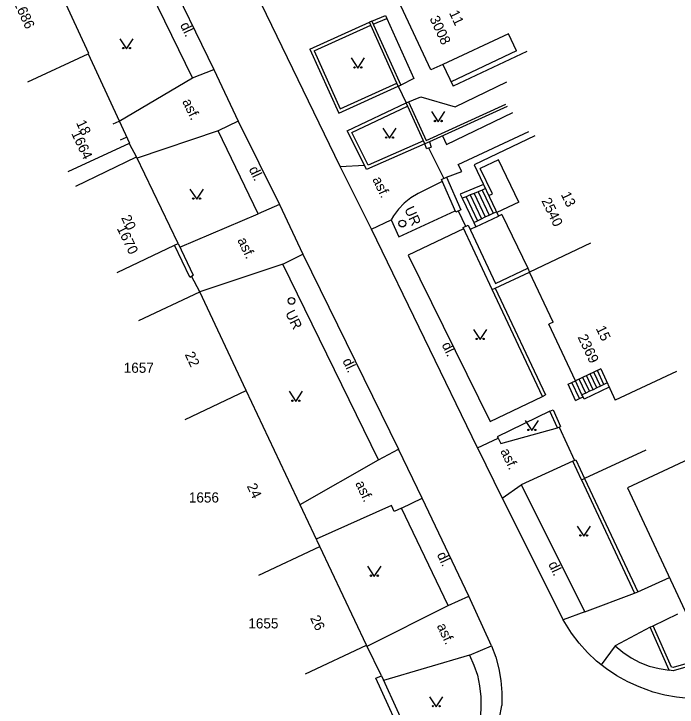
# Model space of a CAD drawing. Extents: x -584400 to -581602, y -1210894 to -1208793.
# Drawn here: x -583212.7 to -583163.5, y -1209753.8 to -1209702.4 of the extents above; entities that cross this region are included whole.
import ezdxf

# ---------------------------------------------------------------- set-up
doc = ezdxf.new("R2010")
doc.units = 0
for name, color, linetype in [('BUDOVY_MĚŘ', 7, 'Continuous'), ('POMOC_POPIS', 7, 'Continuous'), ('ROZHRANÍ_PLOCH', 7, 'Continuous'), ('ZN_DOPLŇKOVÉ', 7, 'Continuous'), ('ZN_KULTUR', 7, 'Continuous'), ('Č_POPIS_EVID', 7, 'Continuous')]:
    doc.layers.add(name, color=color, linetype=linetype)

msp = doc.modelspace()

# ---------------------------------------------------------------- linework, layer by layer
at = {"layer": 'BUDOVY_MĚŘ'}
for points in [[(-583207.21, -1209705.38), (-583207.17, -1209705.36), (-583212.56, -1209693.7)], [(-583180.91, -1209706.16), (-583181.8, -1209706.57), (-583185.32, -1209699.05)], [(-583211.7, -1209707.46), (-583207.21, -1209705.38)], [(-583207.21, -1209705.38), (-583204.16, -1209712)], [(-583174.69, -1209705.2), (-583180.16, -1209707.76)], [(-583180.91, -1209706.16), (-583180.16, -1209707.76)], [(-583174.09, -1209711.44), (-583178.6, -1209713.59), (-583176.78, -1209717.39)], [(-583208.71, -1209714.09), (-583204.16, -1209712)], [(-583208.13, -1209715.17), (-583203.63, -1209713.01)], [(-583205.06, -1209721.58), (-583200.82, -1209719.55), (-583200.55, -1209719.42), (-583203.63, -1209713.01)], [(-583176.55, -1209717.28), (-583176.78, -1209717.39)], [(-583176.55, -1209717.28), (-583174.62, -1209721.26), (-583174.49, -1209721.54)], [(-583169.96, -1209719.41), (-583174.49, -1209721.54)], [(-583172.74, -1209725.25), (-583174.49, -1209721.54)], [(-583203.47, -1209725.14), (-583198.94, -1209723.01)], [(-583195.49, -1209730.33), (-583198.94, -1209723.01)], [(-583172.74, -1209725.25), (-583173.06, -1209725.4)], [(-583169.21, -1209728.72), (-583171.08, -1209729.6), (-583173.06, -1209725.4)], [(-583169.21, -1209728.72), (-583168.13, -1209731.04)], [(-583163.6, -1209728.92), (-583168.13, -1209731.04)], [(-583200.02, -1209732.46), (-583195.49, -1209730.33)], [(-583190.04, -1209741.87), (-583195.49, -1209730.33)], [(-583162.69, -1209735.4), (-583167.22, -1209737.52), (-583162.6, -1209747.4)], [(-583194.56, -1209744.01), (-583190.04, -1209741.87)], [(-583191.1, -1209751.32), (-583186.58, -1209749.18), (-583190.04, -1209741.87)]]:
    msp.add_lwpolyline(points, dxfattribs=at)
at = {"layer": 'ROZHRANÍ_PLOCH'}
for points in [[(-583188.54, -1209713.73), (-583206.86, -1209675.87), (-583209.5, -1209670.38)], [(-583201.53, -1209699.05), (-583197.9, -1209706.54)], [(-583199.49, -1209707.15), (-583203.06, -1209699.78)], [(-583186.19, -1209702.95), (-583185.18, -1209702.53), (-583185.08, -1209702.76)], [(-583186.08, -1209703.18), (-583185.08, -1209702.76)], [(-583185.08, -1209702.76), (-583183.06, -1209707.21), (-583184.04, -1209707.69)], [(-583190.79, -1209705.03), (-583186.36, -1209703.03)], [(-583190.46, -1209705.15), (-583186.26, -1209703.25)], [(-583175.45, -1209705.16), (-583176.05, -1209703.88), (-583180.91, -1209706.16)], [(-583190.79, -1209705.03), (-583188.64, -1209709.77), (-583184.22, -1209707.77), (-583183.63, -1209709.01)], [(-583190.46, -1209705.15), (-583188.52, -1209709.44), (-583184.32, -1209707.54)], [(-583175.45, -1209705.16), (-583180.31, -1209707.44)], [(-583199.49, -1209707.15), (-583197.9, -1209706.54)], [(-583197.9, -1209706.54), (-583196.1, -1209710.36)], [(-583204.92, -1209710.36), (-583199.49, -1209707.15)], [(-583183.63, -1209709.01), (-583182.54, -1209708.57), (-583180.01, -1209709.29), (-583176.18, -1209707.45)], [(-583186.73, -1209713.63), (-583188.01, -1209711.07), (-583183.63, -1209709.01)], [(-583182.36, -1209711.81), (-583186.46, -1209713.62), (-583187.67, -1209711.19), (-583183.53, -1209709.24)], [(-583180.94, -1209711.44), (-583180.64, -1209712.08), (-583175.73, -1209709.71)], [(-583205.37, -1209710.57), (-583204.92, -1209710.36)], [(-583196.1, -1209710.36), (-583197.59, -1209711.08)], [(-583196.1, -1209710.36), (-583193.03, -1209716.54)], [(-583197.59, -1209711.08), (-583203.58, -1209713.1)], [(-583194.6, -1209717.23), (-583197.59, -1209711.08)], [(-583180.65, -1209714.52), (-583179.52, -1209714.08), (-583179.77, -1209713.57), (-583174.53, -1209711.14)], [(-583204.83, -1209711.75), (-583204.37, -1209711.54)], [(-583182.26, -1209712.04), (-583186.58, -1209713.94), (-583186.73, -1209713.63)], [(-583188.54, -1209713.73), (-583186.73, -1209713.63)], [(-583175.29, -1209716.37), (-583176.79, -1209713.22), (-583178.14, -1209713.86)], [(-583186.22, -1209718.37), (-583188.54, -1209713.73)], [(-583177.51, -1209715.87), (-583177.24, -1209715.74), (-583178.14, -1209713.86)], [(-583180.97, -1209714.83), (-583182.76, -1209715.72), (-583183.29, -1209716.04), (-583183.78, -1209716.43), (-583184.2, -1209716.88), (-583184.57, -1209717.38), (-583184.74, -1209717.68)], [(-583177.9, -1209715.05), (-583179.63, -1209715.77), (-583179.48, -1209716.08)], [(-583178.6, -1209715.71), (-583178.89, -1209715.83)], [(-583178.3, -1209715.59), (-583178.6, -1209715.71)], [(-583178.6, -1209715.71), (-583177.77, -1209717.46)], [(-583178.01, -1209715.47), (-583178.3, -1209715.59)], [(-583178.3, -1209715.59), (-583177.48, -1209717.32)], [(-583177.76, -1209715.36), (-583178.01, -1209715.47)], [(-583178.01, -1209715.47), (-583177.19, -1209717.19)], [(-583179.19, -1209715.96), (-583179.48, -1209716.08)], [(-583179.48, -1209716.08), (-583178.63, -1209717.88)], [(-583178.89, -1209715.83), (-583179.19, -1209715.96)], [(-583179.19, -1209715.96), (-583178.35, -1209717.74)], [(-583178.89, -1209715.83), (-583178.06, -1209717.6)], [(-583193.03, -1209716.54), (-583194.6, -1209717.23)], [(-583193.03, -1209716.54), (-583191.29, -1209720.21)], [(-583175.29, -1209716.37), (-583176.91, -1209717.14)], [(-583200.42, -1209719.69), (-583194.6, -1209717.23)], [(-583184.74, -1209717.68), (-583184.17, -1209718.93), (-583180, -1209717.01)], [(-583177.48, -1209717.32), (-583177.19, -1209717.19)], [(-583177.19, -1209717.19), (-583176.94, -1209717.07)], [(-583186.22, -1209718.37), (-583184.74, -1209717.68)], [(-583178.63, -1209717.88), (-583178.35, -1209717.74)], [(-583178.48, -1209718.2), (-583176.78, -1209717.39)], [(-583178.35, -1209717.74), (-583178.06, -1209717.6)], [(-583178.06, -1209717.6), (-583177.77, -1209717.46)], [(-583177.77, -1209717.46), (-583177.48, -1209717.32)], [(-583178.48, -1209718.2), (-583178.89, -1209718.38)], [(-583178.63, -1209717.88), (-583178.48, -1209718.2)], [(-583178.35, -1209734.57), (-583186.22, -1209718.37)], [(-583179.38, -1209718.34), (-583183.48, -1209720.29), (-583177.41, -1209732.62), (-583173.53, -1209730.76)], [(-583192.78, -1209720.96), (-583191.29, -1209720.21)], [(-583191.29, -1209720.21), (-583184.21, -1209734.66)], [(-583192.78, -1209720.96), (-583198.94, -1209723.01)], [(-583185.7, -1209735.45), (-583192.78, -1209720.96)], [(-583169.51, -1209730.13), (-583170, -1209729.09)], [(-583169.24, -1209730), (-583169.73, -1209728.96)], [(-583168.97, -1209729.87), (-583169.45, -1209728.84)], [(-583171.36, -1209729.73), (-583171.08, -1209729.6)], [(-583170.6, -1209730.64), (-583171.08, -1209729.6)], [(-583170.32, -1209730.51), (-583170.81, -1209729.47)], [(-583170.05, -1209730.38), (-583170.54, -1209729.35)], [(-583169.78, -1209730.26), (-583170.27, -1209729.22)], [(-583171.07, -1209731.05), (-583171.63, -1209729.86), (-583171.36, -1209729.73)], [(-583170.79, -1209730.92), (-583171.36, -1209729.73)], [(-583168.58, -1209730.08), (-583170.45, -1209730.96), (-583170.52, -1209730.8)], [(-583169.51, -1209730.13), (-583169.78, -1209730.26)], [(-583169.24, -1209730), (-583169.51, -1209730.13)], [(-583168.97, -1209729.87), (-583169.24, -1209730)], [(-583168.73, -1209729.76), (-583168.97, -1209729.87)], [(-583170.32, -1209730.51), (-583170.6, -1209730.64)], [(-583170.52, -1209730.8), (-583170.6, -1209730.64)], [(-583170.05, -1209730.38), (-583170.32, -1209730.51)], [(-583169.78, -1209730.26), (-583170.05, -1209730.38)], [(-583171.07, -1209731.05), (-583170.79, -1209730.92)], [(-583170.79, -1209730.92), (-583170.52, -1209730.8)], [(-583172.98, -1209731.84), (-583176.88, -1209733.75), (-583176.82, -1209733.86)], [(-583176.82, -1209733.86), (-583176.63, -1209734.25), (-583172.42, -1209733.08)], [(-583178.35, -1209734.57), (-583176.82, -1209733.86)], [(-583185.7, -1209735.45), (-583184.21, -1209734.66)], [(-583182.45, -1209738.29), (-583184.21, -1209734.66)], [(-583178.35, -1209734.57), (-583176.53, -1209738.29)], [(-583191.5, -1209738.76), (-583185.7, -1209735.45)], [(-583171.27, -1209735.56), (-583175.11, -1209737.31)], [(-583176.53, -1209738.29), (-583175.11, -1209737.31)], [(-583175.11, -1209737.31), (-583170.38, -1209746.72)], [(-583183.98, -1209739.03), (-583182.45, -1209738.29)], [(-583179, -1209745.57), (-583182.45, -1209738.29)], [(-583176.53, -1209738.29), (-583171.99, -1209747.3)], [(-583183.98, -1209739.03), (-583184.53, -1209739.29), (-583184.72, -1209738.83), (-583190.3, -1209741.33)], [(-583180.53, -1209746.26), (-583183.98, -1209739.03)], [(-583166.47, -1209745.24), (-583164.1, -1209744.18)], [(-583132.11, -1209744.84), (-583134.13, -1209745.42), (-583160.05, -1209752.88), (-583160.92, -1209753.04), (-583161.81, -1209753.12), (-583162.7, -1209753.13), (-583163.59, -1209753.05), (-583164.47, -1209752.9), (-583165.33, -1209752.66), (-583166.35, -1209752.28), (-583167.2, -1209751.91), (-583168.02, -1209751.46), (-583168.79, -1209750.95), (-583169.52, -1209750.37), (-583170.2, -1209749.73), (-583170.82, -1209749.04), (-583171.38, -1209748.3), (-583171.99, -1209747.3)], [(-583170.38, -1209746.72), (-583166.7, -1209745.34)], [(-583180.53, -1209746.26), (-583179, -1209745.57)], [(-583177.31, -1209749.24), (-583179, -1209745.57)], [(-583186.54, -1209749.27), (-583180.53, -1209746.26)], [(-583170.38, -1209746.72), (-583171.99, -1209747.3)], [(-583165.32, -1209747.75), (-583163.49, -1209746.87)], [(-583165.55, -1209747.85), (-583168.14, -1209749.24)], [(-583178.93, -1209749.92), (-583177.31, -1209749.24)], [(-583177.31, -1209749.24), (-583177, -1209750.08), (-583176.77, -1209750.94), (-583176.62, -1209751.81), (-583176.54, -1209752.7), (-583176.55, -1209753.66)], [(-583168.14, -1209749.24), (-583169.19, -1209750.65)], [(-583168.14, -1209749.24), (-583167.57, -1209749.72), (-583166.95, -1209750.13), (-583166.3, -1209750.47), (-583165.61, -1209750.74), (-583164.89, -1209750.93), (-583164.14, -1209751.05)], [(-583178.93, -1209749.92), (-583185.31, -1209751.81)], [(-583178.93, -1209749.92), (-583178.61, -1209750.66), (-583178.36, -1209751.42), (-583178.2, -1209752.21), (-583178.1, -1209753.01), (-583178.09, -1209753.81), (-583178.13, -1209754.37)], [(-583180.31, -1209759.03), (-583179.67, -1209758.67), (-583179.07, -1209758.25), (-583178.52, -1209757.76), (-583178.03, -1209757.22), (-583177.6, -1209756.62), (-583177.23, -1209755.99), (-583176.94, -1209755.31), (-583176.72, -1209754.61), (-583176.55, -1209753.66)]]:
    msp.add_lwpolyline(points, dxfattribs=at)
at = {"layer": 'ZN_DOPLŇKOVÉ'}
for points in [[(-583186.19, -1209702.95), (-583186.36, -1209703.03)], [(-583184.22, -1209707.77), (-583186.36, -1209703.03)], [(-583186.19, -1209702.95), (-583184.04, -1209707.69)], [(-583184.22, -1209707.77), (-583184.04, -1209707.69)], [(-583181.92, -1209711.89), (-583182.26, -1209712.04), (-583183.63, -1209709.01)], [(-583183.46, -1209708.94), (-583182.16, -1209711.79), (-583176.24, -1209709.1)], [(-583176.16, -1209709.27), (-583181.92, -1209711.89)], [(-583204.12, -1209712.09), (-583204.16, -1209712)], [(-583203.63, -1209713.01), (-583204.12, -1209712.09)], [(-583182.14, -1209712.39), (-583182.26, -1209712.04)], [(-583181.92, -1209711.89), (-583181.79, -1209712.28)], [(-583182.14, -1209712.39), (-583181.79, -1209712.28)], [(-583181.97, -1209712.34), (-583180.84, -1209714.61)], [(-583179.58, -1209716.93), (-583179.96, -1209717.1), (-583181.03, -1209714.69), (-583180.65, -1209714.52)], [(-583180.65, -1209714.52), (-583179.58, -1209716.93)], [(-583179.77, -1209717.01), (-583179.23, -1209718.15)], [(-583177.26, -1209722.84), (-583179.42, -1209718.24), (-583179.04, -1209718.06)], [(-583179.04, -1209718.06), (-583177.01, -1209722.38), (-583174.62, -1209721.26)], [(-583199.69, -1209721.91), (-583200.82, -1209719.55)], [(-583200.55, -1209719.42), (-583199.42, -1209721.78)], [(-583199.69, -1209721.91), (-583199.42, -1209721.78)], [(-583198.94, -1209723.01), (-583199.55, -1209721.85)], [(-583177.03, -1209722.73), (-583174.49, -1209721.54)], [(-583177.26, -1209722.84), (-583177.03, -1209722.73)], [(-583173.53, -1209730.76), (-583177.26, -1209722.84)], [(-583177.03, -1209722.73), (-583173.31, -1209730.65)], [(-583173.53, -1209730.76), (-583173.31, -1209730.65)], [(-583172.42, -1209733.08), (-583172.98, -1209731.84), (-583172.75, -1209731.74)], [(-583172.75, -1209731.74), (-583172.19, -1209732.98)], [(-583172.42, -1209733.08), (-583172.19, -1209732.98)], [(-583172.3, -1209733.03), (-583171.16, -1209735.51)], [(-583165.87, -1209734.75), (-583170.41, -1209736.85)], [(-583170.63, -1209736.95), (-583171.27, -1209735.56), (-583171.05, -1209735.46)], [(-583171.05, -1209735.46), (-583170.41, -1209736.85)], [(-583170.63, -1209736.95), (-583170.41, -1209736.85)], [(-583170.63, -1209736.95), (-583166.7, -1209745.34), (-583166.47, -1209745.24)], [(-583170.41, -1209736.85), (-583166.47, -1209745.24)], [(-583153.87, -1209747.97), (-583153.8, -1209748.21), (-583163.83, -1209751.1), (-583164.14, -1209751.05), (-583165.55, -1209747.85), (-583165.32, -1209747.75)], [(-583153.87, -1209747.97), (-583163.85, -1209750.84), (-583163.97, -1209750.82), (-583165.32, -1209747.75)], [(-583185.47, -1209751.46), (-583186.58, -1209749.18)], [(-583185.88, -1209751.64), (-583185.47, -1209751.46), (-583182.94, -1209756.99), (-583191.41, -1209760.79), (-583191.54, -1209760.52)], [(-583191.19, -1209760.19), (-583183.54, -1209756.77), (-583185.88, -1209751.64)]]:
    msp.add_lwpolyline(points, dxfattribs=at)
for centre, radius in [((-583183.921, -1209717.95), 0.25), ((-583183.921, -1209717.95), 0.0005), ((-583192.14, -1209723.68), 0.25), ((-583192.14, -1209723.68), 0.0005)]:
    msp.add_circle(centre, radius, dxfattribs=at)
at = {"layer": 'ZN_KULTUR'}
for points in [[(-583204.87, -1209704.25), (-583204.37, -1209705), (-583203.87, -1209704.25)], [(-583187.72, -1209705.68), (-583187.22, -1209706.43), (-583186.72, -1209705.68)], [(-583181.76, -1209709.65), (-583181.26, -1209710.4), (-583180.76, -1209709.65)], [(-583185.37, -1209710.88), (-583184.87, -1209711.63), (-583184.37, -1209710.88)], [(-583199.67, -1209715.4), (-583199.17, -1209716.15), (-583198.67, -1209715.4)], [(-583178.65, -1209725.8), (-583178.15, -1209726.55), (-583177.65, -1209725.8)], [(-583192.32, -1209730.38), (-583191.82, -1209731.13), (-583191.32, -1209730.38)], [(-583174.82, -1209732.54), (-583174.32, -1209733.29), (-583173.82, -1209732.54)], [(-583170.97, -1209740.36), (-583170.47, -1209741.11), (-583169.97, -1209740.36)], [(-583186.5, -1209743.34), (-583186, -1209744.09), (-583185.5, -1209743.34)], [(-583181.91, -1209753.01), (-583181.41, -1209753.76), (-583180.91, -1209753.01)]]:
    msp.add_lwpolyline(points, dxfattribs=at)
for centre in [(-583204.62, -1209704.95), (-583204.12, -1209704.95), (-583187.47, -1209706.38), (-583186.97, -1209706.38), (-583181.51, -1209710.35), (-583181.01, -1209710.35), (-583185.12, -1209711.58), (-583184.62, -1209711.58), (-583199.42, -1209716.1), (-583198.92, -1209716.1), (-583178.4, -1209726.5), (-583177.9, -1209726.5), (-583192.07, -1209731.08), (-583191.57, -1209731.08), (-583174.57, -1209733.24), (-583174.07, -1209733.24), (-583170.72, -1209741.06), (-583170.22, -1209741.06), (-583186.25, -1209744.04), (-583185.75, -1209744.04), (-583181.66, -1209753.71), (-583181.16, -1209753.71)]:
    msp.add_circle(centre, 0.05, dxfattribs=at)

# ---------------------------------------------------------------- texts
at = {"layer": 'POMOC_POPIS'}
for s, rotation, p in [('dl.', 295.2685, (-583200.42, -1209703.23)), ('asf.', 295.5673, (-583200.26, -1209708.9)), ('dl.', 295.2685, (-583195.32, -1209713.91)), ('asf.', 295.5673, (-583186.16, -1209714.67)), ('UR', 294.6534, (-583183.79, -1209716.88)), ('asf.', 295.5673, (-583196.17, -1209719.18)), ('UR', 296.0312, (-583192.62, -1209724.58)), ('dl.', 295.5673, (-583181.02, -1209726.93)), ('dl.', 295.2685, (-583188.38, -1209728.12)), ('asf.', 295.5673, (-583176.67, -1209734.81)), ('asf.', 295.2685, (-583187.43, -1209737.2)), ('dl.', 295.2685, (-583181.38, -1209742.48)), ('dl.', 295.5673, (-583173.12, -1209743.18)), ('asf.', 295.2685, (-583181.38, -1209747.76))]:
    msp.add_text(s, height=0.75, rotation=rotation, dxfattribs=at).set_placement(p)
at = {"layer": 'Č_POPIS_EVID'}
for s, rotation, p in [('1686', 294.824, (-583212.76, -1209701.58)), ('11', 295.0848, (-583180.47, -1209702.34)), ('3008', 295.0848, (-583181.92, -1209702.76)), ('18', 295.1729, (-583208.13, -1209710.48)), ('1664', 295.1729, (-583208.49, -1209711.26)), ('13', 295.8611, (-583172.18, -1209715.8)), ('2540', 295.8611, (-583173.63, -1209716.25)), ('20', 295.5957, (-583204.79, -1209717.52)), ('1670', 295.5957, (-583205.11, -1209718.3)), ('15', 295.1505, (-583169.59, -1209725.72)), ('2369', 295.1505, (-583170.94, -1209726.36)), ('22', 295.2475, (-583200.07, -1209727.65)), ('24', 295.2685, (-583195.47, -1209737.4)), ('26', 295.2685, (-583190.78, -1209747.18))]:
    msp.add_text(s, height=0.75, rotation=rotation, dxfattribs=at).set_placement(p)
for s, p in [('1657', (-583204.58, -1209729.01)), ('1656', (-583199.75, -1209738.62)), ('1655', (-583195.34, -1209747.95))]:
    msp.add_text(s, height=0.75, dxfattribs=at).set_placement(p)

doc.saveas('drawing.dxf')
